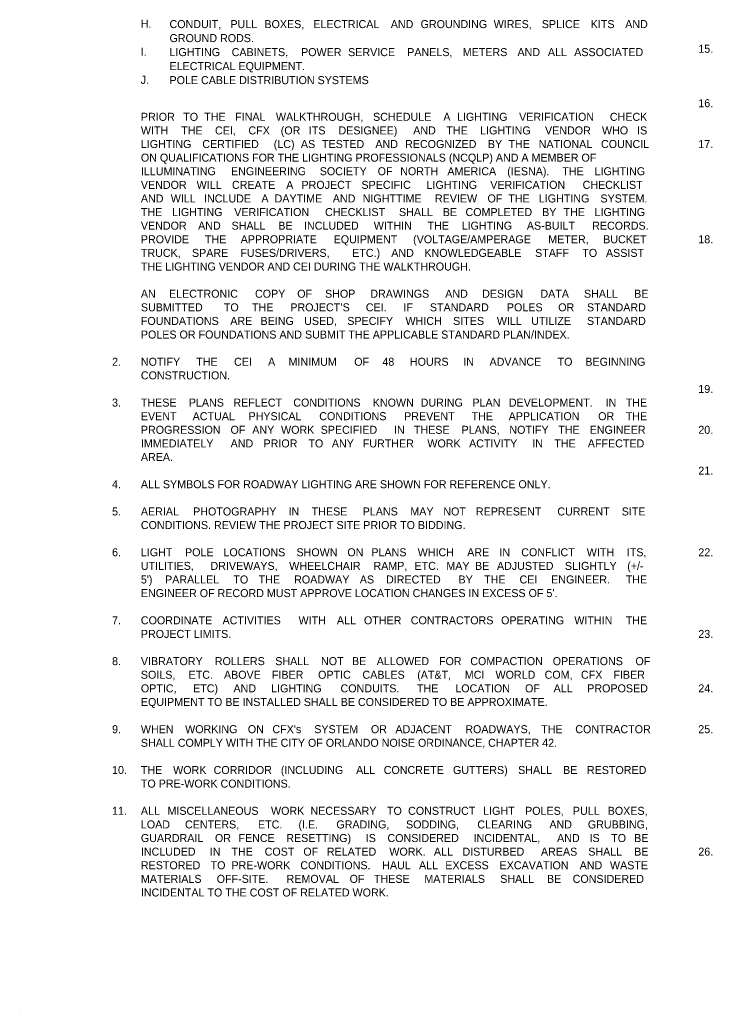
# Model space of a CAD drawing. Extents: x -55 to 2471539, y -90 to 3608906.
# Drawn here: x -55 to 551, y -90 to 775 of the extents above; entities that cross this region are included whole.
import ezdxf

# ---------------------------------------------------------------- set-up
doc = ezdxf.new("R2010")
doc.units = 0
doc.layers.add('TextMinor', color=7, linetype='Continuous')
doc.layers.add('XSCell', color=7, linetype='Continuous')

msp = doc.modelspace()

# ---------------------------------------------------------------- linework, layer by layer
at = {"layer": 'TextMinor'}
msp.add_line((-55, -90), (-55, -90), dxfattribs=at)

# ---------------------------------------------------------------- texts
at = {"layer": 'XSCell'}
for s, p in [('H.', (50.72, 768.23)), ('CONDUIT, ', (75.97, 767.96)), ('PULL ', (129.25, 767.96)), ('BOXES, ', (158.98, 767.96)), ('ELECTRICAL ', (201.78, 767.96)), ('AND ', (269.51, 767.96)), ('GROUNDING ', (295.61, 767.96)), ('WIRES, ', (359.52, 767.96)), ('SPLICE ', (401.61, 767.96)), ('KITS ', (444.38, 767.96)), ('AND ', (474.57, 767.96)), ('GROUND RODS.', (75.97, 755.71)), ('15.', (538.51, 746.38)), ('I.', (50.72, 743.73)), ('LIGHTING ', (75.97, 743.46)), ('CABINETS, ', (130.32, 743.46)), ('POWER ', (191.04, 743.46)), ('SERVICE ', (232.19, 743.46)), ('PANELS, ', (283.88, 743.46)), ('METERS ', (332.46, 743.46)), ('AND ', (380.33, 743.46)), ('ALL ', (406.91, 743.46)), ('ASSOCIATED ', (429.97, 743.46)), ('ELECTRICAL EQUIPMENT.', (75.97, 731.21)), ('J.', (50.72, 719.23)), ('POLE CABLE DISTRIBUTION SYSTEMS', (75.97, 718.96)), ('16.', (538.51, 698.78)), ('PRIOR ', (50.92, 686.88)), ('TO ', (87.97, 686.88)), ('THE ', (106.26, 686.88)), ('FINAL ', (133.38, 686.88)), ('WALKTHROUGH, ', (169.06, 686.88)), ('SCHEDULE ', (254.01, 686.88)), ('A ', (315.47, 686.88)), ('LIGHTING ', (327.43, 686.88)), ('VERIFICATION ', (381.77, 686.88)), ('CHECK ', (461.12, 686.88)), ('WITH ', (50.92, 674.98)), ('THE ', (86.21, 674.98)), ('CEI, ', (115.75, 674.98)), ('CFX ', (145, 674.98)), ('(OR ', (173.26, 674.98)), ('ITS ', (197.82, 674.98)), ('DESIGNEE) ', (223.77, 674.98)), ('AND ', (289.13, 674.98)), ('THE ', (318.13, 674.98)), ('LIGHTING ', (347.67, 674.98)), ('VENDOR ', (404.44, 674.98)), ('WHO ', (454.24, 674.98)), ('IS ', (484.99, 674.98)), ('LIGHTING ', (50.92, 663.08)), ('CERTIFIED ', (104.66, 663.08)), ('(LC) ', (167.14, 663.08)), ('AS ', (190.89, 663.08)), ('TESTED ', (209.32, 663.08)), ('AND ', (256.04, 663.08)), ('RECOGNIZED ', (282.02, 663.08)), ('BY ', (354.46, 663.08)), ('THE ', (372.41, 663.08)), ('NATIONAL ', (398.92, 663.08)), ('COUNCIL ', (453.39, 663.08)), ('17.', (538.51, 663.08)), ('ON QUALIFICATIONS FOR THE LIGHTING PROFESSIONALS (NCQLP) AND A MEMBER OF ', (50.92, 651.18)), ('ILLUMINATING ', (50.92, 639.28)), ('ENGINEERING ', (129.76, 639.28)), ('SOCIETY ', (207.39, 639.28)), ('OF ', (258.02, 639.28)), ('NORTH ', (277.76, 639.28)), ('AMERICA ', (319.04, 639.28)), ('(IESNA). ', (371.35, 639.28)), ('THE ', (419.56, 639.28)), ('LIGHTING ', (447.79, 639.28)), ('VENDOR ', (50.92, 627.38)), ('WILL ', (99.69, 627.38)), ('CREATE ', (130.61, 627.38)), ('A ', (178.05, 627.38)), ('PROJECT ', (191.4, 627.38)), ('SPECIFIC ', (243.88, 627.38)), ('LIGHTING ', (300.8, 627.38)), ('VERIFICATION ', (356.54, 627.38)), ('CHECKLIST ', (437.29, 627.38)), ('AND ', (50.92, 615.48)), ('WILL ', (77.06, 615.48)), ('INCLUDE ', (106.15, 615.48)), ('A ', (156.37, 615.48)), ('DAYTIME ', (167.89, 615.48)), ('AND ', (218.8, 615.48)), ('NIGHTTIME ', (244.95, 615.48)), ('REVIEW ', (308.14, 615.48)), ('OF ', (354.11, 615.48)), ('THE ', (372.31, 615.48)), ('LIGHTING ', (399, 615.48)), ('SYSTEM. ', (452.91, 615.48)), ('THE ', (50.92, 603.58)), ('LIGHTING ', (78.14, 603.58)), ('VERIFICATION ', (132.59, 603.58)), ('CHECKLIST ', (212.05, 603.58)), ('SHALL ', (276.7, 603.58)), ('BE ', (315.01, 603.58)), ('COMPLETED ', (334.87, 603.58)), ('BY ', (401.91, 603.58)), ('THE ', (420.57, 603.58)), ('LIGHTING ', (447.79, 603.58)), ('VENDOR ', (50.92, 591.68)), ('AND ', (100.99, 591.68)), ('SHALL ', (130.26, 591.68)), ('BE ', (171.16, 591.68)), ('INCLUDED ', (193.6, 591.68)), ('WITHIN ', (254.63, 591.68)), ('THE ', (301.66, 591.68)), ('LIGHTING ', (331.48, 591.68)), ('AS-BUILT ', (388.52, 591.68)), ('RECORDS. ', (445.65, 591.68)), ('PROVIDE ', (50.92, 579.78)), ('THE ', (106.93, 579.78)), ('APPROPRIATE ', (138.23, 579.78)), ('EQUIPMENT ', (219.54, 579.78)), ('(VOLTAGE/AMPERAGE ', (289.04, 579.78)), ('METER, ', (407.26, 579.78)), ('BUCKET ', (455.29, 579.78)), ('18.', (538.51, 579.78)), ('TRUCK, ', (50.92, 567.88)), ('SPARE ', (95.61, 567.88)), ('FUSES/DRIVERS, ', (137.94, 567.88)), ('ETC.) ', (235.78, 567.88)), ('AND ', (269.92, 567.88)), ('KNOWLEDGEABLE ', (298.92, 567.88)), ('STAFF ', (395.78, 567.88)), ('TO ', (437.04, 567.88)), ('ASSIST ', (457.75, 567.88)), ('THE LIGHTING VENDOR AND CEI DURING THE WALKTHROUGH. ', (50.92, 555.98)), ('AN ', (50.92, 532.18)), ('ELECTRONIC ', (75.49, 532.18)), ('COPY ', (150.75, 532.18)), ('OF ', (187.7, 532.18)), ('SHOP ', (212.01, 532.18)), ('DRAWINGS ', (251.62, 532.18)), ('AND ', (317.13, 532.18)), ('DESIGN ', (349.39, 532.18)), ('DATA ', (400.39, 532.18)), ('SHALL ', (438.51, 532.18)), ('BE ', (482.39, 532.18)), ('SUBMITTED ', (50.92, 520.28)), ('TO ', (123.51, 520.28)), ('THE ', (148.15, 520.28)), ('PROJECT’S ', (181.63, 520.28)), ('CEI. ', (247.7, 520.28)), ('IF ', (280.58, 520.28)), ('STANDARD ', (303.72, 520.28)), ('POLES ', (371.09, 520.28)), ('OR ', (415.99, 520.28)), ('STANDARD ', (441.13, 520.28)), ('FOUNDATIONS ', (50.92, 508.38)), ('ARE ', (129.11, 508.38)), ('BEING ', (155.61, 508.38)), ('USED, ', (193.77, 508.38)), ('SPECIFY ', (231.5, 508.38)), ('WHICH ', (282.39, 508.38)), ('SITES ', (324.05, 508.38)), ('WILL ', (362.31, 508.38)), ('UTILIZE ', (392.36, 508.38)), ('STANDARD ', (441.13, 508.38)), ('POLES OR FOUNDATIONS AND SUBMIT THE APPLICABLE STANDARD PLAN/INDEX.', (50.92, 496.48)), ('2.', (25.72, 472.68)), ('NOTIFY ', (50.92, 472.68)), ('THE ', (99.31, 472.68)), ('CEI ', (132.42, 472.68)), ('A ', (162.18, 472.68)), ('MINIMUM ', (180.13, 472.68)), ('OF ', (237.55, 472.68)), ('48 ', (262.17, 472.68)), ('HOURS ', (286.27, 472.68)), ('IN ', (332.9, 472.68)), ('ADVANCE ', (355.9, 472.68)), ('TO ', (415.42, 472.68)), ('BEGINNING ', (439.69, 472.68)), ('CONSTRUCTION.', (50.92, 460.78)), ('19.', (538.51, 448.88)), ('3.', (25.72, 436.98)), ('THESE ', (50.92, 436.98)), ('PLANS ', (92.83, 436.98)), ('REFLECT ', (131.8, 436.98)), ('CONDITIONS ', (184.27, 436.98)), ('KNOWN ', (253.77, 436.98)), ('DURING ', (295.65, 436.98)), ('PLAN ', (340.92, 436.98)), ('DEVELOPMENT. ', (372.81, 436.98)), ('IN ', (457.44, 436.98)), ('THE ', (475.03, 436.98)), ('EVENT ', (50.92, 425.08)), ('ACTUAL ', (96.2, 425.08)), ('PHYSICAL ', (145.08, 425.08)), ('CONDITIONS ', (206.94, 425.08)), ('PREVENT ', (281.18, 425.08)), ('THE ', (340.2, 425.08)), ('APPLICATION ', (372.64, 425.08)), ('OR ', (450.92, 425.08)), ('THE ', (475.03, 425.08)), ('PROGRESSION ', (50.92, 413.18)), ('OF ', (129.35, 413.18)), ('ANY ', (148.35, 413.18)), ('WORK ', (173.54, 413.18)), ('SPECIFIED ', (208.2, 413.18)), ('IN ', (272.35, 413.18)), ('THESE ', (289.73, 413.18)), ('PLANS, ', (331.43, 413.18)), ('NOTIFY ', (373.24, 413.18)), ('THE ', (416.02, 413.18)), ('ENGINEER ', (443.5, 413.18)), ('20.', (538.51, 413.18)), ('IMMEDIATELY ', (50.92, 401.28)), ('AND ', (129.41, 401.28)), ('PRIOR ', (158.2, 401.28)), ('TO ', (197.46, 401.28)), ('ANY ', (217.96, 401.28)), ('FURTHER ', (244.99, 401.28)), ('WORK ', (301.5, 401.28)), ('ACTIVITY ', (338.01, 401.28)), ('IN ', (393.31, 401.28)), ('THE ', (412.53, 401.28)), ('AFFECTED ', (441.86, 401.28)), ('AREA.', (50.92, 389.38)), ('21.', (538.51, 377.48)), ('4.', (25.72, 365.58)), ('ALL SYMBOLS FOR ROADWAY LIGHTING ARE SHOWN FOR REFERENCE ONLY.', (50.92, 365.58)), ('5.', (25.72, 341.78)), ('AERIAL ', (50.92, 341.78)), ('PHOTOGRAPHY ', (96.65, 341.78)), ('IN ', (180.07, 341.78)), ('THESE ', (200.35, 341.78)), ('PLANS ', (244.95, 341.78)), ('MAY ', (286.61, 341.78)), ('NOT ', (315.49, 341.78)), ('REPRESENT ', (343.98, 341.78)), ('CURRENT ', (415.21, 341.78)), ('SITE ', (471.49, 341.78)), ('CONDITIONS. REVIEW THE PROJECT SITE PRIOR TO BIDDING.', (50.92, 329.88)), ('6.', (25.72, 306.08)), ('LIGHT ', (50.92, 306.08)), ('POLE ', (89.54, 306.08)), ('LOCATIONS ', (123.15, 306.08)), ('SHOWN ', (187.03, 306.08)), ('ON ', (231.54, 306.08)), ('PLANS ', (252.54, 306.08)), ('WHICH ', (293.07, 306.08)), ('ARE ', (336.35, 306.08)), ('IN ', (364.47, 306.08)), ('CONFLICT ', (383.63, 306.08)), ('WITH ', (440.93, 306.08)), ('ITS, ', (475.95, 306.08)), ('22.', (538.51, 306.08)), ('UTILITIES, ', (50.92, 294.18)), ('DRIVEWAYS, ', (111.78, 294.18)), ('WHEELCHAIR ', (180.68, 294.18)), ('RAMP, ', (254.36, 294.18)), ('ETC. ', (290.3, 294.18)), ('MAY ', (318.12, 294.18)), ('BE ', (343.19, 294.18)), ('ADJUSTED ', (362.4, 294.18)), ('SLIGHTLY ', (421.83, 294.18)), ('(+/- ', (476.32, 294.18)), ("5') ", (50.92, 282.28)), ('PARALLEL ', (72.07, 282.28)), ('TO ', (131.83, 282.28)), ('THE ', (153.99, 282.28)), ('ROADWAY ', (184.97, 282.28)), ('AS ', (242.43, 282.28)), ('DIRECTED ', (265.33, 282.28)), ('BY ', (328.73, 282.28)), ('THE ', (351.14, 282.28)), ('CEI ', (382.13, 282.28)), ('ENGINEER. ', (409.76, 282.28)), ('THE ', (475.03, 282.28)), ('ENGINEER OF RECORD MUST APPROVE LOCATION CHANGES IN EXCESS OF 5’.', (50.92, 270.38)), ('7.', (25.72, 246.58)), ('COORDINATE ', (50.92, 246.58)), ('ACTIVITIES ', (122.34, 246.58)), ('WITH ', (188.86, 246.58)), ('ALL ', (222.36, 246.58)), ('OTHER ', (246.03, 246.58)), ('CONTRACTORS ', (287.02, 246.58)), ('OPERATING ', (365.99, 246.58)), ('WITHIN ', (430.06, 246.58)), ('THE ', (475.03, 246.58)), ('PROJECT LIMITS.', (50.92, 234.68)), ('23.', (538.51, 234.68)), ('8.', (25.72, 210.88)), ('VIBRATORY ', (50.92, 210.88)), ('ROLLERS ', (115.6, 210.88)), ('SHALL ', (168.44, 210.88)), ('NOT ', (208.51, 210.88)), ('BE ', (235.59, 210.88)), ('ALLOWED ', (257.21, 210.88)), ('FOR ', (311.68, 210.88)), ('COMPACTION ', (339.05, 210.88)), ('OPERATIONS ', (411.16, 210.88)), ('OF ', (483.52, 210.88)), ('SOILS, ', (50.92, 198.98)), ('ETC. ', (92.67, 198.98)), ('ABOVE ', (123.59, 198.98)), ('FIBER ', (165.51, 198.98)), ('OPTIC ', (205.94, 198.98)), ('CABLES ', (244.74, 198.98)), ('(AT&T, ', (292.64, 198.98)), ('MCI ', (334.23, 198.98)), ('WORLD ', (361.13, 198.98)), ('COM, ', (404.06, 198.98)), ('CFX ', (435.87, 198.98)), ('FIBER ', (464.26, 198.98)), ('OPTIC, ', (50.92, 187.08)), ('ETC) ', (96.58, 187.08)), ('AND ', (131.91, 187.08)), ('LIGHTING ', (164.85, 187.08)), ('CONDUITS. ', (225.56, 187.08)), ('THE ', (292.46, 187.08)), ('LOCATION ', (325.94, 187.08)), ('OF ', (386.95, 187.08)), ('ALL ', (411.94, 187.08)), ('PROPOSED ', (441.35, 187.08)), ('24.', (538.51, 187.08)), ('EQUIPMENT TO BE INSTALLED SHALL BE CONSIDERED TO BE APPROXIMATE.', (50.92, 175.18)), ('9.', (25.72, 151.38)), ('WHEN ', (50.92, 151.38)), ('WORKING ', (89.63, 151.38)), ('ON ', (144.47, 151.38)), ("CFX's ", (166, 151.38)), ('SYSTEM ', (202.59, 151.38)), ('OR ', (252.13, 151.38)), ('ADJACENT ', (273.59, 151.38)), ('ROADWAYS, ', (334.69, 151.38)), ('THE ', (401.09, 151.38)), ('CONTRACTOR ', (430.88, 151.38)), ('25.', (538.51, 151.38)), ('SHALL COMPLY WITH THE CITY OF ORLANDO NOISE ORDINANCE, CHAPTER 42.', (50.92, 139.48)), ('10.', (25.72, 115.68)), ('THE ', (50.92, 115.68)), ('WORK ', (79.14, 115.68)), ('CORRIDOR ', (114.54, 115.68)), ('(INCLUDING ', (173.34, 115.68)), ('ALL ', (239.19, 115.68)), ('CONCRETE ', (263.34, 115.68)), ('GUTTERS) ', (323.94, 115.68)), ('SHALL ', (380.9, 115.68)), ('BE ', (420.21, 115.68)), ('RESTORED ', (441.07, 115.68)), ('TO PRE-WORK CONDITIONS.', (50.92, 103.78)), ('11.', (25.72, 79.98)), ('ALL ', (50.92, 79.98)), ('MISCELLANEOUS ', (74.2, 79.98)), ('WORK ', (164.73, 79.98)), ('NECESSARY ', (199.25, 79.98)), ('TO ', (266.17, 79.98)), ('CONSTRUCT ', (284.68, 79.98)), ('LIGHT ', (350.29, 79.98)), ('POLES, ', (386.99, 79.98)), ('PULL ', (428.81, 79.98)), ('BOXES, ', (459.25, 79.98)), ('LOAD ', (50.92, 68.08)), ('CENTERS, ', (89.55, 68.08)), ('ETC. ', (153.33, 68.08)), ('(I.E. ', (188.77, 68.08)), ('GRADING, ', (221.91, 68.08)), ('SODDING, ', (282.85, 68.08)), ('CLEARING ', (345.23, 68.08)), ('AND ', (408.25, 68.08)), ('GRUBBING, ', (441.91, 68.08)), ('GUARDRAIL ', (50.92, 56.18)), ('OR ', (115.72, 56.18)), ('FENCE ', (136.3, 56.18)), ('RESETTING) ', (178.12, 56.18)), ('IS ', (247.66, 56.18)), ('CONSIDERED ', (266.61, 56.18)), ('INCIDENTAL, ', (341.94, 56.18)), ('AND ', (414.99, 56.18)), ('IS ', (443.37, 56.18)), ('TO ', (462.31, 56.18)), ('BE ', (482.39, 56.18)), ('INCLUDED ', (50.92, 44.28)), ('IN ', (111.19, 44.28)), ('THE ', (130.13, 44.28)), ('COST ', (159.19, 44.28)), ('OF ', (193.05, 44.28)), ('RELATED ', (213.61, 44.28)), ('WORK. ', (268.26, 44.28)), ('ALL ', (307.24, 44.28)), ('DISTURBED ', (332.23, 44.28)), ('AREAS ', (400.86, 44.28)), ('SHALL ', (442.26, 44.28)), ('BE ', (482.39, 44.28)), ('26.', (538.51, 44.28)), ('RESTORED ', (50.92, 32.38)), ('TO ', (111.92, 32.38)), ('PRE-WORK ', (130.13, 32.38)), ('CONDITIONS. ', (190.4, 32.38)), ('HAUL ', (262, 32.38)), ('ALL ', (294.21, 32.38)), ('EXCESS ', (317.19, 32.38)), ('EXCAVATION ', (364.68, 32.38)), ('AND ', (434.74, 32.38)), ('WASTE ', (461.25, 32.38)), ('MATERIALS ', (50.92, 20.48)), ('OFF-SITE. ', (117.26, 20.48)), ('REMOVAL ', (178.36, 20.48)), ('OF ', (233.51, 20.48)), ('THESE ', (254.85, 20.48)), ('MATERIALS ', (298.89, 20.48)), ('SHALL ', (365.23, 20.48)), ('BE ', (406.14, 20.48)), ('CONSIDERED ', (428.6, 20.48)), ('INCIDENTAL TO THE COST OF RELATED WORK.', (50.92, 8.58))]:
    msp.add_text(s, height=7, dxfattribs=at).set_placement(p)

doc.saveas('drawing.dxf')
